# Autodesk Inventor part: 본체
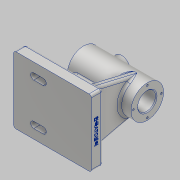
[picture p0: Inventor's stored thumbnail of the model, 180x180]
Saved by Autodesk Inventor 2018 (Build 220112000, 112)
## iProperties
Created: 2022-06
Part Number: 본체
Material: 알루미늄 6061
Document SubType Name: Modeling
Designer: home
Density: 2.7 g/cm^3
Appearance: 알루미늄 - 평지
Mass: 638.767 g
Surface Area: 515.995 cm^2
Volume: 236.58 cm^3
Author: home
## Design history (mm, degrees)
sketch "스케치1"
  geometry: L1 (50, -43)-(-50, -43); L2 (-50, -43)-(-50, 43); L3 (-50, 43)-(50, 43); L4 (50, 43)-(50, -43); L5 (50, -43)-(-50, 43); 2 further points
  constraints: 10 end point, 2 parallel, 1 coincident, 1 horizontal, 1 midpoint, 1 perpendicular
  dimensions: "d0" = 100 distance of L1.start L1.end; "d1" = 86 distance of L1.end L2.end
extrude "돌출1" new body sketch "스케치1" distance "d2" = 15; taper "d3" = 0 deg
sketch "스케치2"
  geometry: L1 (-49, 72)-(53, 72); L2 (-50, 0)-(50, 0) reference; L3 (-32, 86.5)-(30, 86.5); L4 (30, 86.5)-(30, 83.5); L5 (30, 83.5)-(50, 83.5); L6 (50, 83.5)-(50, 93); L7 (50, 93)-(-32, 93); L8 (-32, 93)-(-32, 86.5); 2 further points
  constraints: 14 end point, 5 perpendicular, 2 horizontal, 1 vertical alignment
  dimensions: "d4" = 72 distance between parallel lines of L2 L1; "d5" = 82 distance of L6.end L7.end; "d6" = 42 diameter of L7 L1; "d7" = 23 diameter of L5 L1; "d8" = 29 diameter of L3 L1; "d9" = 62 distance of L3.start L3.end; "d15" = 3 distance from line of L1.end L6; "d16" = 99 distance from line of L1.start L6
revolve "회전1" sketch "스케치2" stored, may be unused: angle "d10" = 90 deg
node "작업 평면1"
sketch "스케치3"
  geometry: L1 (-50, -43)-(-50, 43) reference; L2 (-32, -21)-(-32, 21) reference; C1 r 11 at (-7, 0); 1 further point
  constraints: 1 centre point, 1 horizontal alignment
  dimensions: "d12" = 22 diameter of C1; "d14" = 25 distance from line of C1.centre L2
extrude "돌출2" join sketch "스케치3" stored distance "d17" = 15; taper "d18" = 0 deg
sketch "스케치4"
  geometry: C1 r 11 at (0, 0) reference; 1 further point
hole "구멍1" sketch "스케치4" at (0, 0) diameter "d19" = 4.917; stored, may be unused: countersink angle "d23" = 90 deg, drill point angle "d25" = 118 deg; dims "d20" = 12, "d21" = 14, "d22" = 4, "d24" = 17.1
sketch "스케치5"
  geometry: C1 r 11.5 at (0, 0) reference; 2 further points
  constraints: 1 vertical alignment
  dimensions: "d26" = 18 distance of point (0, 18) C1.centre
hole "구멍2" sketch "스케치5" at (0, 18) diameter "d27" = 2.459; stored, may be unused: countersink angle "d31" = 90 deg, drill point angle "d33" = 118 deg; dims "d28" = 8, "d29" = 10, "d30" = 4, "d32" = 10
sketch "스케치6"
  geometry: C1 r 11.5 at (0, 0) reference; 2 further points
  constraints: 1 vertical alignment
  dimensions: "d37" = 18 distance of point (0, 18) C1.centre
hole "구멍3" sketch "스케치6" at (0, 18) diameter "d38" = 2.459; stored, may be unused: countersink angle "d42" = 90 deg, drill point angle "d44" = 118 deg; dims "d39" = 8, "d40" = 10, "d41" = 4, "d43" = 10
node "작업 평면2"
sketch "스케치7"
  geometry: L1 (86, 15)-(0, 15) reference; L2 (8, 15)-(22.559, 76.814); L3 (63.441, 76.814)-(78, 15); L4 (0, 0)-(0, 15) reference; L5 (86, 0)-(86, 15) reference; L6 (8, 15)-(78, 15); A1 r 21 centre (43, 72) between (22.559, 76.814) and (63.441, 76.814) reference; 1 further point
  constraints: 6 end point, 2 point on circle, 2 point on line, 2 tangent, 1 collinear
  dimensions: "d49" = 8 distance from line of L4 L2.start; "d50" = 8 distance from line of L5 L3.end
feature "리브1" sketch "스케치7" dims "d51" = 1, "d52" = 10, "d53" = 0, "d54" = 0, "d55" = 1, "d56" = 1
sketch "스케치8"
  geometry: L1 (-21.897, 51)-(-35, 15); L2 (50, 15)-(-50, 15) reference; L3 (-50, 0)-(-50, 15) reference; L4 (-32, 51)-(50, 51) reference; 1 further point
  constraints: 2 end point, 2 point on line
  dimensions: "d57" = 70 deg angle of L2 L1; "d58" = 15 distance from line of L3 L1.end
feature "리브2" sketch "스케치8" dims "d59" = 1, "d60" = 10, "d61" = 0, "d62" = 0, "d63" = 1, "d64" = 1
sketch "스케치9"
  geometry: L1 (-24, 27)-(-12, 27); L2 (-24, 20)-(-12, 20); L3 (-12, 34)-(-24, 34); L4 (-50, -43)-(-50, 43) reference; L5 (-50, 43)-(50, 43) reference; A1 r 7 centre (-24, 27) between (-24, 34) and (-24, 20); A2 r 7 centre (-12, 27) between (-12, 20) and (-12, 34); 2 further points
  constraints: 8 end point, 4 point on circle, 4 tangent, 2 centre point, 1 horizontal, 1 midpoint, 1 parallel
  dimensions: "d65" = 12 distance of L1.start L1.end; "d66" = 26 distance from line of L4 L1.start; "d67" = 7 radius of A1; "d68" = 16 distance from line of L5 point (-18, 27)
extrude "돌출3" join sketch "스케치9" distance "d69" = 3; taper "d70" = 0 deg
sketch "스케치10"
  geometry: L1 (-24, 27)-(-12, 27); L2 (-24, 23)-(-12, 23); L3 (-12, 31)-(-24, 31); L4 (50, 43)-(-50, 43) reference; A1 r 7 centre (-24, 27) between (-24, 34) and (-24, 20) reference; A2 r 7 centre (-12, 27) between (-12, 20) and (-12, 34) reference; A3 r 4 centre (-24, 27) between (-24, 31) and (-24, 23); A4 r 4 centre (-12, 27) between (-12, 23) and (-12, 31); 3 further points
  constraints: 8 end point, 4 point on circle, 4 tangent, 2 centre point, 1 horizontal, 1 midpoint, 1 parallel
  dimensions: "d71" = 8 diameter of A4; "d74" = 16 distance between parallel lines of L1 L4 (derived)
extrude "돌출4" cut sketch "스케치10" extent not by distance; stored distance "d72" = 3; taper "d73" = 0 deg
sketch "스케치11"
  geometry: L1 (86, 0)-(0, 0) reference; 3 further points
  constraints: 1 midpoint, 1 vertical alignment, 1 other
  dimensions: "d75" = 6 distance from line of L1 point (43, 6)
feature "엠보싱1" sketch "스케치11" dims "d0" = 100, "d1" = 86, "d76" = 0.5, "d77" = 0
fillet "모깎기1" dims "d78" = 3
fillet "모깎기2" dims "d79" = 3
fillet "모깎기3" dims "d80" = 3
fillet "모깎기4" dims "d81" = 3
chamfer "모따기1" distance "d82" = 1; stored, may be unused: second distance "d83" = 2, angle "d84" = 45 deg
fillet "모깎기5" dims "d85" = 3
fillet "모깎기6" dims "d86" = 3
fillet "모깎기7" dims "d87" = 1
node "솔리드1"
pattern_circular "원형 패턴1" dims angle "d35" = 360 deg
pattern_circular "원형 패턴2" dims angle "d46" = 360 deg
mirror "미러1"
node "투영된 루프1"
other parameters: "d11" = -96, "d48" = -15
